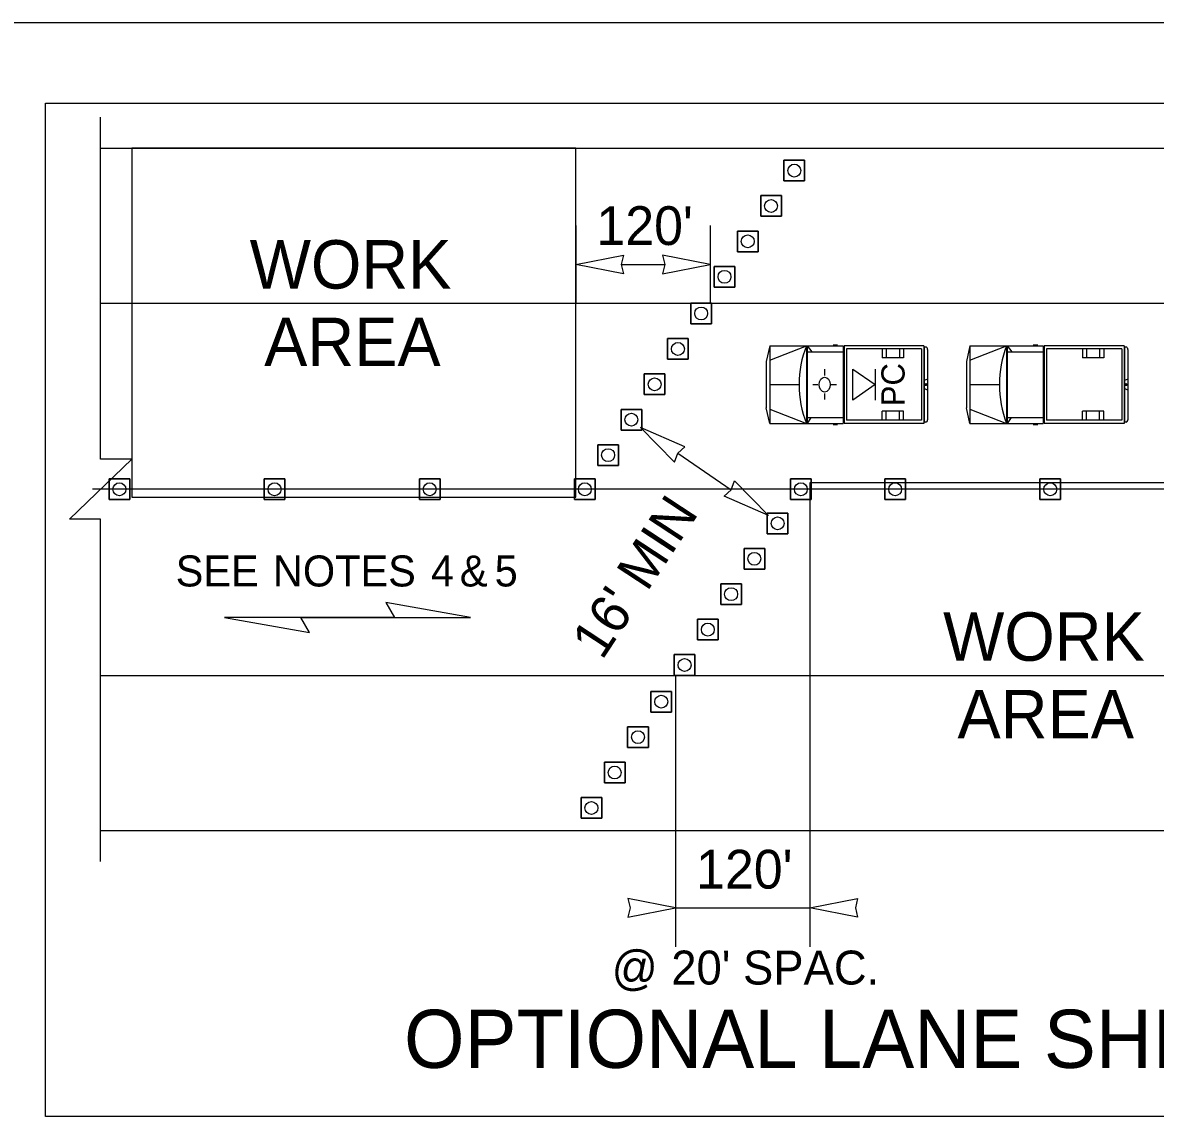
# Model space of a CAD drawing. Extents: x 99999.1 to 100095.7, y 99995 to 100010.7.
# Drawn here: x 100004.94 to 100007.276, y 100003.475 to 100005.732 of the extents above; entities that cross this region are included whole.
import ezdxf

# ---------------------------------------------------------------- set-up
doc = ezdxf.new("R2010")
doc.units = 0
for name, color, linetype in [('RD_ED_ShoulderPavedEdge', 7, 'Continuous'), ('RD_MK_LineEdgeWhite', 7, 'Continuous'), ('RD_MK_LineSkipCenter', 7, 'Continuous'), ('SH_DE_DetailHeading2Text', 7, 'Continuous'), ('SH_TI_Tables', 7, 'Continuous'), ('TR_WZ_MotoristVehicle', 7, 'Continuous'), ('TR_WZ_PortableSignMountBlk-Wht', 7, 'Continuous'), ('TR_WZ_TrafficCone', 7, 'Continuous'), ('TR_WZ_WorkAreaLabel', 7, 'Continuous'), ('TR_WZ_WorkZoneDetails', 7, 'Continuous'), ('TR_WZ_WorkZoneTextCurrent', 7, 'Continuous')]:
    doc.layers.add(name, color=color, linetype=linetype)

msp = doc.modelspace()

# ---------------------------------------------------------------- linework, layer by layer
at = {"layer": 'RD_ED_ShoulderPavedEdge'}
for p, q in [((100000.1076, 100005.7323), (100015.6424, 100005.7323)), ((100005.1009, 100005.4735), (100009.0183, 100005.4735)), ((100005.1009, 100004.0655), (100009.0183, 100004.0655))]:
    msp.add_line(p, q, dxfattribs=at)
at = {"layer": 'RD_MK_LineEdgeWhite'}
for p, q in [((100005.1009, 100005.1535), (100009.0183, 100005.1535)), ((100005.1009, 100004.3855), (100009.0183, 100004.3855))]:
    msp.add_line(p, q, dxfattribs=at)
at = {"layer": 'RD_MK_LineSkipCenter'}
msp.add_lwpolyline([(100009.0017, 100004.7695), (100005.0844, 100004.7695)], dxfattribs=at)
at = {"layer": 'SH_TI_Tables'}
msp.add_lwpolyline([(100004.9869, 100005.5662), (100009.1323, 100005.5662), (100009.1323, 100003.4755), (100004.9869, 100003.4755)], close=True, dxfattribs=at)
at = {"layer": 'TR_WZ_MotoristVehicle'}
for p, q in [((100006.481, 100005.0655), (100006.4736, 100005.0332)), ((100006.481, 100005.0655), (100006.481, 100004.9055)), ((100006.481, 100005.0655), (100006.6321, 100005.0655)), ((100006.481, 100005.0362), (100006.5566, 100005.0655)), ((100006.5566, 100005.0655), (100006.5566, 100004.9055)), ((100006.5579, 100005.0655), (100006.5579, 100004.9055)), ((100006.5579, 100005.0655), (100006.5675, 100005.0531)), ((100006.6115, 100005.0677), (100006.6206, 100005.0677)), ((100006.6321, 100005.0655), (100006.6321, 100004.9055)), ((100006.7989, 100005.0655), (100006.6343, 100005.0655)), ((100006.6343, 100005.0655), (100006.6343, 100004.9055)), ((100006.7942, 100005.0591), (100006.639, 100005.0591)), ((100006.639, 100005.0591), (100006.639, 100004.9119)), ((100006.7132, 100005.0591), (100006.7132, 100005.0407)), ((100006.7211, 100005.0591), (100006.7211, 100005.0407)), ((100006.7483, 100005.0591), (100006.7483, 100005.0407)), ((100006.7571, 100005.0591), (100006.7571, 100005.0407)), ((100006.7942, 100005.0591), (100006.7942, 100004.9119)), ((100006.7989, 100005.0655), (100006.7989, 100004.9055)), ((100006.803, 100005.0629), (100006.7994, 100005.0629)), ((100006.7994, 100005.0629), (100006.7994, 100004.9081)), ((100006.894, 100005.0655), (100006.8866, 100005.0332)), ((100006.894, 100005.0655), (100006.894, 100004.9055)), ((100006.894, 100005.0655), (100007.0451, 100005.0655)), ((100006.894, 100005.0362), (100006.9696, 100005.0655)), ((100006.9696, 100005.0655), (100006.9696, 100004.9055)), ((100006.9709, 100005.0655), (100006.9709, 100004.9055)), ((100006.9709, 100005.0655), (100006.9806, 100005.0531)), ((100007.0245, 100005.0677), (100007.0336, 100005.0677)), ((100007.0451, 100005.0655), (100007.0451, 100004.9055)), ((100007.2119, 100005.0655), (100007.0473, 100005.0655)), ((100007.0473, 100005.0655), (100007.0473, 100004.9055)), ((100007.2072, 100005.0591), (100007.052, 100005.0591)), ((100007.052, 100005.0591), (100007.052, 100004.9119)), ((100007.1262, 100005.0591), (100007.1262, 100005.0407)), ((100007.1341, 100005.0591), (100007.1341, 100005.0407)), ((100007.1614, 100005.0591), (100007.1614, 100005.0407)), ((100007.1701, 100005.0591), (100007.1701, 100005.0407)), ((100007.2072, 100005.0591), (100007.2072, 100004.9119)), ((100007.2119, 100005.0655), (100007.2119, 100004.9055)), ((100007.216, 100005.0629), (100007.2125, 100005.0629)), ((100007.2125, 100005.0629), (100007.2125, 100004.9081)), ((100006.5579, 100005.0531), (100006.6321, 100005.0531)), ((100006.7571, 100005.0407), (100006.7132, 100005.0407)), ((100006.8066, 100005.058), (100006.8066, 100004.913)), ((100006.9709, 100005.0531), (100007.0451, 100005.0531)), ((100007.1701, 100005.0407), (100007.1262, 100005.0407)), ((100007.2196, 100005.058), (100007.2196, 100004.913)), ((100006.4736, 100005.0332), (100006.4736, 100004.9378)), ((100006.5942, 100005.0172), (100006.5942, 100005.0043)), ((100006.8866, 100005.0332), (100006.8866, 100004.9378)), ((100006.8066, 100004.9968), (100006.7994, 100004.9938)), ((100007.2196, 100004.9968), (100007.2125, 100004.9938)), ((100006.481, 100004.9855), (100006.5417, 100004.9855)), ((100006.5701, 100004.9856), (100006.5802, 100004.9856)), ((100006.5948, 100004.9547), (100006.5945, 100004.9668)), ((100006.6055, 100004.9852), (100006.6055, 100004.9852)), ((100006.6189, 100004.9849), (100006.607, 100004.9852)), ((100006.8066, 100004.9742), (100006.7994, 100004.9772)), ((100006.8047, 100004.9855), (100006.8014, 100004.9855)), ((100006.803, 100004.9877), (100006.803, 100004.9832)), ((100006.894, 100004.9855), (100006.9547, 100004.9855)), ((100007.2196, 100004.9742), (100007.2125, 100004.9772)), ((100007.2177, 100004.9855), (100007.2144, 100004.9855)), ((100007.216, 100004.9877), (100007.216, 100004.9832)), ((100006.481, 100004.9055), (100006.4736, 100004.9378)), ((100006.481, 100004.9348), (100006.5566, 100004.9055)), ((100006.7132, 100004.9119), (100006.7132, 100004.9303)), ((100006.7571, 100004.9303), (100006.7132, 100004.9303)), ((100006.7211, 100004.9119), (100006.7211, 100004.9303)), ((100006.7483, 100004.9119), (100006.7483, 100004.9303)), ((100006.7571, 100004.9119), (100006.7571, 100004.9303)), ((100006.894, 100004.9055), (100006.8866, 100004.9378)), ((100006.894, 100004.9348), (100006.9696, 100004.9055)), ((100007.1262, 100004.9119), (100007.1262, 100004.9303)), ((100007.1701, 100004.9303), (100007.1262, 100004.9303)), ((100007.1341, 100004.9119), (100007.1341, 100004.9303)), ((100007.1614, 100004.9119), (100007.1614, 100004.9303)), ((100007.1701, 100004.9119), (100007.1701, 100004.9303)), ((100006.481, 100004.9055), (100006.6321, 100004.9055)), ((100006.5579, 100004.9179), (100006.6321, 100004.9179)), ((100006.5659, 100004.9179), (100006.5579, 100004.9055)), ((100006.6115, 100004.9032), (100006.6206, 100004.9032)), ((100006.7989, 100004.9055), (100006.6343, 100004.9055)), ((100006.7942, 100004.9119), (100006.639, 100004.9119)), ((100006.803, 100004.9081), (100006.7994, 100004.9081)), ((100006.894, 100004.9055), (100007.0451, 100004.9055)), ((100006.9709, 100004.9179), (100007.0451, 100004.9179)), ((100006.9789, 100004.9179), (100006.9709, 100004.9055)), ((100007.0245, 100004.9032), (100007.0336, 100004.9032)), ((100007.2119, 100004.9055), (100007.0473, 100004.9055)), ((100007.2072, 100004.9119), (100007.052, 100004.9119)), ((100007.216, 100004.9081), (100007.2125, 100004.9081))]:
    msp.add_line(p, q, dxfattribs=at)
for centre, major_axis, start_param, end_param in [((100006.6645, 100004.9855), (0, -0.1679), 4.215667, 5.208926), ((100006.803, 100005.058), (0, 0.00488), 4.712389, 6.283185), ((100007.0776, 100004.9855), (0, -0.1679), 4.215667, 5.208926), ((100007.216, 100005.058), (0, 0.00488), 4.712389, 6.283185), ((100006.803, 100004.913), (0, -0.00488), 0, 1.570796), ((100007.216, 100004.913), (0, -0.00488), 0, 1.570796)]:
    msp.add_ellipse(centre, major_axis=major_axis, ratio=0.73155, start_param=start_param, end_param=end_param, dxfattribs=at)
for centre, major_axis in [((100006.5942, 100004.9855), (0, 0.0154)), ((100006.803, 100004.9855), (0, 0.00225)), ((100007.216, 100004.9855), (0, 0.00225))]:
    msp.add_ellipse(centre, major_axis=major_axis, ratio=0.73155, dxfattribs=at)
at = {"layer": 'TR_WZ_PortableSignMountBlk-Wht'}
msp.add_line((100006.6981, 100005.0174), (100006.6981, 100004.9534), dxfattribs=at)
msp.add_lwpolyline([(100006.6981, 100004.9855), (100006.6521, 100004.9534), (100006.6521, 100005.0174)], close=True, dxfattribs=at)
at = {"layer": 'TR_WZ_TrafficCone'}
for points in [[(100006.5103, 100005.4484), (100006.5529, 100005.4484), (100006.5529, 100005.4058), (100006.5103, 100005.4058), (100006.5103, 100005.4484)], [(100006.5103, 100005.4058), (100006.5529, 100005.4058), (100006.5529, 100005.4484), (100006.5103, 100005.4484), (100006.5103, 100005.4058)], [(100006.4623, 100005.3754), (100006.5049, 100005.3754), (100006.5049, 100005.3327), (100006.4623, 100005.3327), (100006.4623, 100005.3754)], [(100006.4623, 100005.3327), (100006.5049, 100005.3327), (100006.5049, 100005.3754), (100006.4623, 100005.3754), (100006.4623, 100005.3327)], [(100006.4143, 100005.3023), (100006.4569, 100005.3023), (100006.4569, 100005.2596), (100006.4143, 100005.2596), (100006.4143, 100005.3023)], [(100006.4143, 100005.2596), (100006.4569, 100005.2596), (100006.4569, 100005.3023), (100006.4143, 100005.3023), (100006.4143, 100005.2596)], [(100006.3663, 100005.2292), (100006.4089, 100005.2292), (100006.4089, 100005.1866), (100006.3663, 100005.1866), (100006.3663, 100005.2292)], [(100006.3663, 100005.1866), (100006.4089, 100005.1866), (100006.4089, 100005.2292), (100006.3663, 100005.2292), (100006.3663, 100005.1866)], [(100006.3609, 100005.1535), (100006.3182, 100005.1535), (100006.3182, 100005.1108), (100006.3609, 100005.1108), (100006.3609, 100005.1535)], [(100006.3609, 100005.1108), (100006.3182, 100005.1108), (100006.3182, 100005.1535), (100006.3609, 100005.1535), (100006.3609, 100005.1108)], [(100006.3129, 100005.0804), (100006.2702, 100005.0804), (100006.2702, 100005.0378), (100006.3129, 100005.0378), (100006.3129, 100005.0804)], [(100006.3129, 100005.0378), (100006.2702, 100005.0378), (100006.2702, 100005.0804), (100006.3129, 100005.0804), (100006.3129, 100005.0378)], [(100006.2649, 100005.0074), (100006.2222, 100005.0074), (100006.2222, 100004.9647), (100006.2649, 100004.9647), (100006.2649, 100005.0074)], [(100006.2649, 100004.9647), (100006.2222, 100004.9647), (100006.2222, 100005.0074), (100006.2649, 100005.0074), (100006.2649, 100004.9647)], [(100006.2169, 100004.9343), (100006.1742, 100004.9343), (100006.1742, 100004.8916), (100006.2169, 100004.8916), (100006.2169, 100004.9343)], [(100006.2169, 100004.8916), (100006.1742, 100004.8916), (100006.1742, 100004.9343), (100006.2169, 100004.9343), (100006.2169, 100004.8916)], [(100006.1689, 100004.8612), (100006.1262, 100004.8612), (100006.1262, 100004.8186), (100006.1689, 100004.8186), (100006.1689, 100004.8612)], [(100006.1689, 100004.8186), (100006.1262, 100004.8186), (100006.1262, 100004.8612), (100006.1689, 100004.8612), (100006.1689, 100004.8186)], [(100005.1183, 100004.7908), (100005.1609, 100004.7908), (100005.1609, 100004.7482), (100005.1183, 100004.7482), (100005.1183, 100004.7908)], [(100005.1183, 100004.7482), (100005.1609, 100004.7482), (100005.1609, 100004.7908), (100005.1183, 100004.7908), (100005.1183, 100004.7482)], [(100005.4383, 100004.7908), (100005.4809, 100004.7908), (100005.4809, 100004.7482), (100005.4383, 100004.7482), (100005.4383, 100004.7908)], [(100005.4383, 100004.7482), (100005.4809, 100004.7482), (100005.4809, 100004.7908), (100005.4383, 100004.7908), (100005.4383, 100004.7482)], [(100005.7583, 100004.7908), (100005.8009, 100004.7908), (100005.8009, 100004.7482), (100005.7583, 100004.7482), (100005.7583, 100004.7908)], [(100005.7583, 100004.7482), (100005.8009, 100004.7482), (100005.8009, 100004.7908), (100005.7583, 100004.7908), (100005.7583, 100004.7482)], [(100006.1209, 100004.7908), (100006.0782, 100004.7908), (100006.0782, 100004.7482), (100006.1209, 100004.7482), (100006.1209, 100004.7908)], [(100006.1209, 100004.7482), (100006.0782, 100004.7482), (100006.0782, 100004.7908), (100006.1209, 100004.7908), (100006.1209, 100004.7482)], [(100006.5665, 100004.7908), (100006.5239, 100004.7908), (100006.5239, 100004.7482), (100006.5665, 100004.7482), (100006.5665, 100004.7908)], [(100006.5665, 100004.7482), (100006.5239, 100004.7482), (100006.5239, 100004.7908), (100006.5665, 100004.7908), (100006.5665, 100004.7482)], [(100006.7183, 100004.7908), (100006.7609, 100004.7908), (100006.7609, 100004.7482), (100006.7183, 100004.7482), (100006.7183, 100004.7908)], [(100006.7183, 100004.7482), (100006.7609, 100004.7482), (100006.7609, 100004.7908), (100006.7183, 100004.7908), (100006.7183, 100004.7482)], [(100007.0383, 100004.7908), (100007.0809, 100004.7908), (100007.0809, 100004.7482), (100007.0383, 100004.7482), (100007.0383, 100004.7908)], [(100007.0383, 100004.7482), (100007.0809, 100004.7482), (100007.0809, 100004.7908), (100007.0383, 100004.7908), (100007.0383, 100004.7482)], [(100006.4759, 100004.6778), (100006.5186, 100004.6778), (100006.5186, 100004.7204), (100006.4759, 100004.7204), (100006.4759, 100004.6778)], [(100006.4759, 100004.7204), (100006.5186, 100004.7204), (100006.5186, 100004.6778), (100006.4759, 100004.6778), (100006.4759, 100004.7204)], [(100006.4279, 100004.6047), (100006.4706, 100004.6047), (100006.4706, 100004.6474), (100006.4279, 100004.6474), (100006.4279, 100004.6047)], [(100006.4279, 100004.6474), (100006.4706, 100004.6474), (100006.4706, 100004.6047), (100006.4279, 100004.6047), (100006.4279, 100004.6474)], [(100006.3799, 100004.5316), (100006.4226, 100004.5316), (100006.4226, 100004.5743), (100006.3799, 100004.5743), (100006.3799, 100004.5316)], [(100006.3799, 100004.5743), (100006.4226, 100004.5743), (100006.4226, 100004.5316), (100006.3799, 100004.5316), (100006.3799, 100004.5743)], [(100006.3319, 100004.4586), (100006.3746, 100004.4586), (100006.3746, 100004.5012), (100006.3319, 100004.5012), (100006.3319, 100004.4586)], [(100006.3319, 100004.5012), (100006.3746, 100004.5012), (100006.3746, 100004.4586), (100006.3319, 100004.4586), (100006.3319, 100004.5012)], [(100006.2839, 100004.3855), (100006.3266, 100004.3855), (100006.3266, 100004.4282), (100006.2839, 100004.4282), (100006.2839, 100004.3855)], [(100006.2839, 100004.4282), (100006.3266, 100004.4282), (100006.3266, 100004.3855), (100006.2839, 100004.3855), (100006.2839, 100004.4282)], [(100006.2359, 100004.3524), (100006.2786, 100004.3524), (100006.2786, 100004.3098), (100006.2359, 100004.3098), (100006.2359, 100004.3524)], [(100006.2359, 100004.3098), (100006.2786, 100004.3098), (100006.2786, 100004.3524), (100006.2359, 100004.3524), (100006.2359, 100004.3098)], [(100006.1879, 100004.2794), (100006.2306, 100004.2794), (100006.2306, 100004.2367), (100006.1879, 100004.2367), (100006.1879, 100004.2794)], [(100006.1879, 100004.2367), (100006.2306, 100004.2367), (100006.2306, 100004.2794), (100006.1879, 100004.2794), (100006.1879, 100004.2367)], [(100006.1399, 100004.2063), (100006.1826, 100004.2063), (100006.1826, 100004.1636), (100006.1399, 100004.1636), (100006.1399, 100004.2063)], [(100006.1399, 100004.1636), (100006.1826, 100004.1636), (100006.1826, 100004.2063), (100006.1399, 100004.2063), (100006.1399, 100004.1636)], [(100006.0919, 100004.1332), (100006.1346, 100004.1332), (100006.1346, 100004.0906), (100006.0919, 100004.0906), (100006.0919, 100004.1332)], [(100006.0919, 100004.0906), (100006.1346, 100004.0906), (100006.1346, 100004.1332), (100006.0919, 100004.1332), (100006.0919, 100004.0906)]]:
    msp.add_lwpolyline(points, dxfattribs=at)
for centre in [(100006.5316, 100005.4271), (100006.4836, 100005.354), (100006.4356, 100005.281), (100006.3876, 100005.2079), (100006.3396, 100005.1322), (100006.2916, 100005.0591), (100006.2436, 100004.986), (100006.1956, 100004.913), (100006.1476, 100004.8399), (100005.1396, 100004.7695), (100005.4596, 100004.7695), (100005.7796, 100004.7695), (100006.0996, 100004.7695), (100006.5452, 100004.7695), (100006.7396, 100004.7695), (100007.0596, 100004.7695), (100006.4973, 100004.6991), (100006.4493, 100004.626), (100006.4013, 100004.553), (100006.3533, 100004.4799), (100006.3053, 100004.4068), (100006.2572, 100004.3311), (100006.2092, 100004.258), (100006.1612, 100004.185), (100006.1132, 100004.1119)]:
    msp.add_circle(centre, 0.0133, dxfattribs=at)
at = {"layer": 'TR_WZ_WorkZoneDetails'}
for p, q in [((100006.0809, 100005.3135), (100006.0809, 100005.1535)), ((100006.3583, 100005.3135), (100006.3583, 100005.1535)), ((100006.1747, 100005.2335), (100006.2645, 100005.2335)), ((100006.2915, 100004.8438), (100006.4014, 100004.7682)), ((100005.5138, 100004.5049), (100005.7067, 100004.5049)), ((100005.7067, 100004.5049), (100005.5138, 100004.5049)), ((100006.2866, 100004.3855), (100006.2866, 100003.8255)), ((100006.5639, 100004.0655), (100006.5639, 100003.8255)), ((100006.2866, 100003.9055), (100006.5639, 100003.9055))]:
    msp.add_line(p, q, dxfattribs=at)
msp.add_lwpolyline([(100005.1009, 100004.0015), (100005.1009, 100004.7075), (100005.0369, 100004.7075), (100005.1649, 100004.8314), (100005.1009, 100004.8314), (100005.1009, 100005.5375)], dxfattribs=at)
for points in [[(100005.1649, 100005.4735), (100005.1649, 100004.7535), (100006.0809, 100004.7535), (100006.0809, 100005.4735)], [(100006.0809, 100005.2335), (100006.1792, 100005.2528), (100006.1747, 100005.2335), (100006.1792, 100005.2142)], [(100006.3583, 100005.2335), (100006.26, 100005.2528), (100006.2645, 100005.2335), (100006.26, 100005.2142)], [(100006.2143, 100004.897), (100006.2843, 100004.8254), (100006.2915, 100004.8438), (100006.3061, 100004.8571)], [(100006.4786, 100004.7151), (100006.3867, 100004.7549), (100006.4014, 100004.7682), (100006.4085, 100004.7867)], [(100006.5639, 100004.7828), (100006.5639, 100004.0655), (100007.5423, 100004.0655), (100007.5423, 100004.7828)], [(100005.8639, 100004.5049), (100005.6889, 100004.5358), (100005.7067, 100004.5049)], [(100005.3566, 100004.5049), (100005.5316, 100004.4741), (100005.5138, 100004.5049)], [(100006.2866, 100003.9055), (100006.1883, 100003.9248), (100006.1928, 100003.9055), (100006.1883, 100003.8862)], [(100006.5639, 100003.9055), (100006.6622, 100003.9248), (100006.6576, 100003.9055), (100006.6622, 100003.8862)]]:
    msp.add_lwpolyline(points, close=True, dxfattribs=at)

# ---------------------------------------------------------------- texts
at = {"layer": 'SH_DE_DetailHeading2Text'}
msp.add_text('OPTIONAL LANE SHIFT DETAIL', height=0.12, rotation=360, dxfattribs=at).set_placement((100005.7267, 100003.5755))
at = {"layer": 'TR_WZ_MotoristVehicle'}
msp.add_text('PC', height=0.048, rotation=90, dxfattribs=at).set_placement((100006.7592, 100004.9407))
at = {"layer": 'TR_WZ_WorkAreaLabel'}
for s, p in [('WORK', (100005.4084, 100005.1835)), ('AREA', (100005.4381, 100005.0235)), ('WORK', (100006.8386, 100004.4155)), ('AREA', (100006.8682, 100004.2555))]:
    msp.add_text(s, height=0.1, dxfattribs=at).set_placement(p)
at = {"layer": 'TR_WZ_WorkZoneTextCurrent'}
for s, height, rotation, p in [("120'", 0.08, 360, (100006.1235, 100005.2735)), ("16' MIN", 0.08, 56.6977, (100006.1351, 100004.415)), ("120'", 0.08, 360, (100006.3291, 100003.9455)), ('@', 0.07, 360, (100006.155, 100003.7475)), ("20' SPAC.", 0.07, 360, (100006.2779, 100003.7475))]:
    msp.add_text(s, height=height, rotation=rotation, dxfattribs=at).set_placement(p)
for s, p in [('SEE', (100005.2557, 100004.5689)), ('NOTES', (100005.4562, 100004.5689)), ('4', (100005.7822, 100004.5689)), ('&', (100005.8417, 100004.5689)), ('5', (100005.9136, 100004.5689))]:
    msp.add_text(s, height=0.064, dxfattribs=at).set_placement(p)

doc.saveas('drawing.dxf')
